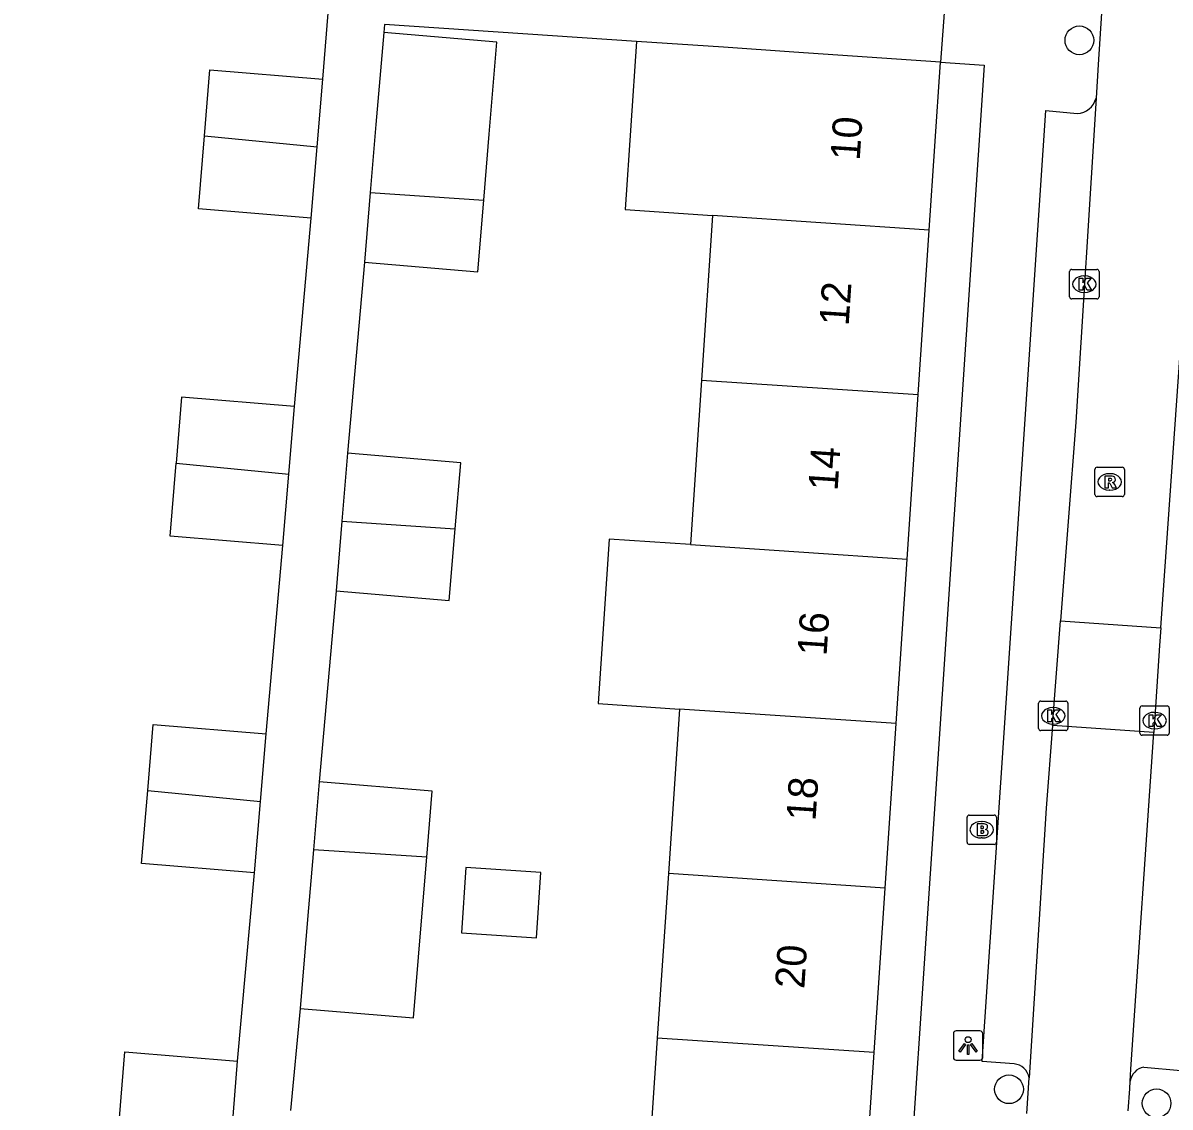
# Model space of a CAD drawing. Extents: x 162250 to 162654, y 380744 to 381605.
# Drawn here: x 162338.01 to 162377.07, y 380830.57 to 380867.49 of the extents above; entities that cross this region are included whole.
import ezdxf

# ---------------------------------------------------------------- set-up
doc = ezdxf.new("R2010")
doc.units = 0
for name, color, linetype in [('IMGEO_Boom', 7, 'Continuous'), ('IMGEO_Brandkraan', 7, 'Continuous'), ('IMGEO_Kolk', 7, 'Continuous'), ('IMGEO_Lichtpunt', 7, 'Continuous'), ('IMGEO_Pand', 7, 'Continuous'), ('IMGEO_Pand_nummerreeks', 7, 'Continuous'), ('IMGEO_Rijbaan_lokaal_open', 7, 'Continuous'), ('IMGEO_Rioolput', 7, 'Continuous'), ('IMGEO_Voetpad_open', 7, 'Continuous')]:
    doc.layers.add(name, color=color, linetype=linetype)

msp = doc.modelspace()

# ---------------------------------------------------------------- linework, layer by layer
at = {"layer": 'IMGEO_Boom'}
for centre in [(162373.988, 380866.894), (162371.59, 380831.172), (162376.616, 380830.694)]:
    msp.add_circle(centre, 0.489, dxfattribs=at)
at = {"layer": 'IMGEO_Brandkraan'}
for p, q in [((162370.162, 380839.584), (162370.162, 380840.436)), ((162370.237, 380840.51), (162371.089, 380840.51)), ((162370.65, 380840.29), (162370.675, 380840.29)), ((162371.163, 380840.436), (162371.163, 380839.584)), ((162371.089, 380839.51), (162370.237, 380839.51)), ((162370.673, 380839.73), (162370.648, 380839.73))]:
    msp.add_line(p, q, dxfattribs=at)
for points in [[(162370.162, 380839.584), (162370.162, 380840.436)], [(162370.237, 380840.51), (162371.089, 380840.51)], [(162370.51, 380840.21), (162370.51, 380839.81), (162370.723, 380839.81)], [(162370.741, 380840.21), (162370.51, 380840.21)], [(162371.163, 380840.436), (162371.163, 380839.584)], [(162370.689, 380840.129), (162370.635, 380840.129), (162370.635, 380840.053)], [(162370.635, 380840.053), (162370.688, 380840.053)], [(162370.697, 380839.977), (162370.635, 380839.977), (162370.635, 380839.896)], [(162370.635, 380839.896), (162370.697, 380839.896)], [(162371.089, 380839.51), (162370.237, 380839.51)]]:
    msp.add_lwpolyline(points, dxfattribs=at)
for centre, radius, start, end in [((162370.239, 380840.434), 0.0765, 91.552, 178.448), ((162370.239, 380840.434), 0.0765, 91.552, 178.448), ((162370.745, 380840.065), 0.145, 59.4692, 91.5367), ((162370.77, 380840.112), 0.0922, 285.5137, 58.1501), ((162371.087, 380840.434), 0.0765, 1.552, 88.448), ((162371.087, 380840.434), 0.0765, 1.552, 88.448), ((162370.69, 380840.091), 0.0379, 267.8285, 90.9355), ((162370.698, 380839.936), 0.0404, 269.8759, 90.5077), ((162370.729, 380840.061), 0.251, 268.6676, 293.5347), ((162370.775, 380839.92), 0.105, 301.3115, 78.989), ((162370.239, 380839.586), 0.0765, 181.552, 268.448), ((162370.239, 380839.586), 0.0765, 181.552, 268.448), ((162371.087, 380839.586), 0.0765, 271.552, 358.448), ((162371.087, 380839.586), 0.0765, 271.552, 358.448)]:
    msp.add_arc(centre, radius, start, end, dxfattribs=at)
for centre, major_axis, ratio, start_param, end_param in [((162370.649, 380840.01), (-0.387, 0.002), 0.722429, 4.712389, 7.853982), ((162370.674, 380840.01), (-0.39, 0.002), 0.717154, 1.570796, 4.712389)]:
    msp.add_ellipse(centre, major_axis=major_axis, ratio=ratio, start_param=start_param, end_param=end_param, dxfattribs=at)
at = {"layer": 'IMGEO_Kolk'}
for p, q in [((162373.656, 380858.164), (162373.656, 380859.016)), ((162373.731, 380859.09), (162374.583, 380859.09)), ((162374.657, 380859.016), (162374.657, 380858.164)), ((162374.144, 380858.87), (162374.169, 380858.87)), ((162374.167, 380858.31), (162374.142, 380858.31)), ((162374.583, 380858.09), (162373.731, 380858.09)), ((162372.597, 380843.464), (162372.597, 380844.316)), ((162372.672, 380844.39), (162373.524, 380844.39)), ((162373.085, 380844.17), (162373.11, 380844.17)), ((162373.598, 380844.316), (162373.598, 380843.464)), ((162376.047, 380843.302), (162376.047, 380844.154)), ((162376.122, 380844.228), (162376.974, 380844.228)), ((162377.048, 380844.154), (162377.048, 380843.302)), ((162376.535, 380844.008), (162376.56, 380844.008)), ((162373.524, 380843.39), (162372.672, 380843.39)), ((162373.108, 380843.61), (162373.083, 380843.61)), ((162376.558, 380843.448), (162376.533, 380843.448)), ((162376.974, 380843.228), (162376.122, 380843.228))]:
    msp.add_line(p, q, dxfattribs=at)
for points in [[(162373.656, 380858.164), (162373.656, 380859.016)], [(162373.731, 380859.09), (162374.583, 380859.09)], [(162374.657, 380859.016), (162374.657, 380858.164)], [(162373.977, 380858.79), (162374.1, 380858.79), (162374.1, 380858.639), (162374.23, 380858.79), (162374.394, 380858.79), (162374.248, 380858.639), (162374.401, 380858.39), (162374.249, 380858.39), (162374.164, 380858.554), (162374.1, 380858.487), (162374.1, 380858.39), (162373.977, 380858.39), (162373.977, 380858.79)], [(162374.583, 380858.09), (162373.731, 380858.09)], [(162372.597, 380843.464), (162372.597, 380844.316)], [(162372.672, 380844.39), (162373.524, 380844.39)], [(162372.918, 380844.09), (162373.041, 380844.09), (162373.041, 380843.939), (162373.171, 380844.09), (162373.335, 380844.09), (162373.189, 380843.939), (162373.342, 380843.69), (162373.19, 380843.69), (162373.105, 380843.854), (162373.041, 380843.787), (162373.041, 380843.69), (162372.918, 380843.69), (162372.918, 380844.09)], [(162373.598, 380844.316), (162373.598, 380843.464)], [(162376.047, 380843.302), (162376.047, 380844.154)], [(162376.122, 380844.228), (162376.974, 380844.228)], [(162377.048, 380844.154), (162377.048, 380843.302)], [(162376.368, 380843.928), (162376.491, 380843.928), (162376.491, 380843.777), (162376.621, 380843.928), (162376.785, 380843.928), (162376.639, 380843.777), (162376.792, 380843.528), (162376.64, 380843.528), (162376.555, 380843.692), (162376.491, 380843.625), (162376.491, 380843.528), (162376.368, 380843.528), (162376.368, 380843.928)], [(162373.524, 380843.39), (162372.672, 380843.39)], [(162376.974, 380843.228), (162376.122, 380843.228)]]:
    msp.add_lwpolyline(points, dxfattribs=at)
for centre, start, end in [((162373.733, 380859.014), 91.552, 178.448), ((162373.733, 380859.014), 91.552, 178.448), ((162374.581, 380859.014), 1.552, 88.448), ((162374.581, 380859.014), 1.552, 88.448), ((162373.733, 380858.166), 181.552, 268.448), ((162373.733, 380858.166), 181.552, 268.448), ((162374.581, 380858.166), 271.552, 358.448), ((162374.581, 380858.166), 271.552, 358.448), ((162372.674, 380844.314), 91.552, 178.448), ((162372.674, 380844.314), 91.552, 178.448), ((162373.522, 380844.314), 1.552, 88.448), ((162373.522, 380844.314), 1.552, 88.448), ((162376.124, 380844.152), 91.552, 178.448), ((162376.124, 380844.152), 91.552, 178.448), ((162376.972, 380844.152), 1.552, 88.448), ((162376.972, 380844.152), 1.552, 88.448), ((162372.674, 380843.466), 181.552, 268.448), ((162372.674, 380843.466), 181.552, 268.448), ((162373.522, 380843.466), 271.552, 358.448), ((162373.522, 380843.466), 271.552, 358.448), ((162376.124, 380843.304), 181.552, 268.448), ((162376.124, 380843.304), 181.552, 268.448), ((162376.972, 380843.304), 271.552, 358.448), ((162376.972, 380843.304), 271.552, 358.448)]:
    msp.add_arc(centre, 0.0765, start, end, dxfattribs=at)
for centre, major_axis, ratio, start_param, end_param in [((162374.143, 380858.59), (-0.387, 0.002), 0.722429, 4.712389, 7.853982), ((162374.168, 380858.59), (-0.39, 0.002), 0.717154, 1.570796, 4.712389), ((162373.084, 380843.89), (-0.387, 0.002), 0.722429, 4.712389, 7.853982), ((162373.109, 380843.89), (-0.39, 0.002), 0.717154, 1.570796, 4.712389), ((162376.534, 380843.728), (-0.387, 0.002), 0.722429, 4.712389, 7.853982), ((162376.559, 380843.728), (-0.39, 0.002), 0.717154, 1.570796, 4.712389)]:
    msp.add_ellipse(centre, major_axis=major_axis, ratio=ratio, start_param=start_param, end_param=end_param, dxfattribs=at)
at = {"layer": 'IMGEO_Lichtpunt'}
for p, q in [((162370.601, 380833.159), (162369.793, 380833.159)), ((162370.601, 380833.159), (162369.793, 380833.159)), ((162369.699, 380833.064), (162369.699, 380832.257)), ((162369.699, 380833.064), (162369.699, 380832.257)), ((162370.695, 380832.257), (162370.695, 380833.064)), ((162370.695, 380832.257), (162370.695, 380833.064)), ((162369.793, 380832.163), (162370.601, 380832.163)), ((162369.793, 380832.163), (162370.601, 380832.163))]:
    msp.add_line(p, q, dxfattribs=at)
for points in [[(162370.073, 380832.728), (162370.112, 380832.7), (162369.924, 380832.438), (162369.886, 380832.465), (162370.073, 380832.728)], [(162370.175, 380832.68), (162370.222, 380832.68), (162370.222, 380832.358), (162370.175, 380832.358), (162370.175, 380832.68)], [(162370.285, 380832.7), (162370.323, 380832.727), (162370.51, 380832.465), (162370.471, 380832.437), (162370.285, 380832.7)]]:
    msp.add_lwpolyline(points, dxfattribs=at)
msp.add_circle((162370.198, 380832.862), 0.0994, dxfattribs=at)
for centre, start, end in [((162369.793, 380833.064), 90, 180), ((162369.793, 380833.064), 90, 180), ((162370.601, 380833.064), 0, 90), ((162370.601, 380833.064), 0, 90), ((162369.793, 380832.257), 180, 270), ((162369.793, 380832.257), 180, 270), ((162370.601, 380832.257), 270, 0), ((162370.601, 380832.257), 270, 360)]:
    msp.add_arc(centre, 0.0946, start, end, dxfattribs=at)
at = {"layer": 'IMGEO_Pand'}
for points in [[(162350.298, 380867.159), (162350.036, 380864.023), (162349.843, 380861.713)], [(162353.704, 380861.454), (162353.891, 380863.701), (162354.152, 380866.837), (162350.298, 380867.159)], [(162358.908, 380866.856), (162358.525, 380861.128), (162361.491, 380860.93)], [(162369.257, 380866.155), (162364.269, 380866.488), (162361.874, 380866.658), (162358.908, 380866.856)], [(162368.874, 380860.433), (162369.257, 380866.155)], [(162344.195, 380863.647), (162344.382, 380865.892), (162348.221, 380865.572)], [(162348.029, 380863.266), (162348.221, 380865.572)], [(162347.826, 380860.838), (162343.987, 380861.158), (162344.195, 380863.647)], [(162344.195, 380863.647), (162348.029, 380863.266)], [(162347.826, 380860.838), (162348.029, 380863.266)], [(162349.843, 380861.713), (162349.645, 380859.334)], [(162349.843, 380861.713), (162353.704, 380861.454)], [(162349.645, 380859.334), (162353.5, 380859.013), (162353.704, 380861.454)], [(162361.491, 380860.93), (162361.116, 380855.325)], [(162368.874, 380860.433), (162361.491, 380860.93)], [(162368.499, 380854.829), (162368.874, 380860.433)], [(162361.116, 380855.325), (162360.741, 380849.724)], [(162361.116, 380855.325), (162368.499, 380854.829)], [(162347.256, 380854.422), (162343.417, 380854.742), (162343.23, 380852.498)], [(162368.125, 380849.228), (162368.499, 380854.829)], [(162347.064, 380852.116), (162347.256, 380854.422)], [(162349.067, 380852.831), (162348.874, 380850.521)], [(162352.735, 380850.262), (162352.922, 380852.509), (162349.067, 380852.831)], [(162346.861, 380849.688), (162343.022, 380850.008), (162343.23, 380852.498)], [(162343.23, 380852.498), (162347.064, 380852.116)], [(162346.861, 380849.688), (162347.064, 380852.116)], [(162348.874, 380850.521), (162348.676, 380848.142)], [(162348.874, 380850.521), (162352.735, 380850.262)], [(162348.676, 380848.142), (162352.531, 380847.821), (162352.735, 380850.262)], [(162360.741, 380849.724), (162357.972, 380849.909), (162357.597, 380844.307), (162360.366, 380844.122)], [(162360.741, 380849.724), (162368.125, 380849.228)], [(162367.75, 380843.625), (162368.125, 380849.228)], [(162360.366, 380844.122), (162359.991, 380838.519)], [(162367.75, 380843.625), (162360.366, 380844.122)], [(162342.265, 380841.348), (162342.452, 380843.593), (162346.291, 380843.273)], [(162367.375, 380838.022), (162367.75, 380843.625)], [(162346.099, 380840.967), (162346.291, 380843.273)], [(162345.896, 380838.539), (162342.057, 380838.859), (162342.265, 380841.348)], [(162342.265, 380841.348), (162346.099, 380840.967)], [(162348.099, 380841.641), (162347.906, 380839.331)], [(162351.767, 380839.072), (162351.954, 380841.319), (162348.099, 380841.641)], [(162345.896, 380838.539), (162346.099, 380840.967)], [(162347.906, 380839.331), (162347.708, 380836.952), (162347.456, 380833.924)], [(162347.456, 380833.924), (162351.31, 380833.603), (162351.563, 380836.631), (162351.767, 380839.072)], [(162351.767, 380839.072), (162347.906, 380839.331)], [(162352.948, 380836.504), (162355.498, 380836.333), (162355.647, 380838.554), (162353.097, 380838.726), (162352.948, 380836.504)], [(162359.991, 380838.519), (162359.616, 380832.916)], [(162367.375, 380838.022), (162359.991, 380838.519)], [(162367, 380832.42), (162367.375, 380838.022)], [(162359.616, 380832.916), (162359.241, 380827.313)], [(162367, 380832.42), (162359.616, 380832.916)], [(162341.3, 380830.2), (162341.487, 380832.444), (162345.326, 380832.124)], [(162366.625, 380826.817), (162367, 380832.42)], [(162345.134, 380829.818), (162345.326, 380832.124)]]:
    msp.add_lwpolyline(points, dxfattribs=at)
at = {"layer": 'IMGEO_Rijbaan_lokaal_open'}
for points in [[(162374.744, 380867.824), (162374.627, 380866.068), (162374.555, 380864.924)], [(162374.555, 380864.924), (162373.864, 380853.89), (162373.347, 380847.122)], [(162376.764, 380846.886), (162377.501, 380857.359), (162378.012, 380864.96)], [(162373.075, 380843.562), (162373.347, 380847.122)], [(162373.347, 380847.122), (162376.764, 380846.886)], [(162376.764, 380846.886), (162376.721, 380846.28), (162376.521, 380843.324)], [(162373.075, 380843.562), (162372.859, 380840.742), (162372.276, 380831.566)], [(162376.521, 380843.324), (162373.075, 380843.562)], [(162375.716, 380831.445), (162375.743, 380831.854), (162376.521, 380843.324)], [(162372.199, 380830.348), (162372.276, 380831.566)], [(162375.65, 380830.442), (162375.7, 380831.192), (162375.716, 380831.445)]]:
    msp.add_lwpolyline(points, dxfattribs=at)
at = {"layer": 'IMGEO_Rioolput'}
for p, q in [((162374.518, 380851.431), (162374.518, 380852.283)), ((162374.593, 380852.357), (162375.445, 380852.357)), ((162375.519, 380852.283), (162375.519, 380851.431)), ((162375.006, 380852.137), (162375.031, 380852.137)), ((162375.029, 380851.577), (162375.004, 380851.577)), ((162375.445, 380851.357), (162374.593, 380851.357))]:
    msp.add_line(p, q, dxfattribs=at)
for points in [[(162374.518, 380851.431), (162374.518, 380852.283)], [(162374.593, 380852.357), (162375.445, 380852.357)], [(162375.519, 380852.283), (162375.519, 380851.431)], [(162375.107, 380852.055), (162374.855, 380852.057), (162374.855, 380851.657)], [(162375.033, 380851.976), (162374.979, 380851.976), (162374.979, 380851.895)], [(162374.979, 380851.895), (162375.031, 380851.895)], [(162374.855, 380851.657), (162374.979, 380851.657), (162374.979, 380851.819), (162374.99, 380851.819)], [(162375.037, 380851.79), (162375.108, 380851.657), (162375.248, 380851.657), (162375.183, 380851.783)], [(162375.445, 380851.357), (162374.593, 380851.357)]]:
    msp.add_lwpolyline(points, dxfattribs=at)
for centre, radius, start, end in [((162374.595, 380852.281), 0.0765, 91.552, 178.448), ((162374.595, 380852.281), 0.0765, 91.552, 178.448), ((162375.443, 380852.281), 0.0765, 1.552, 88.448), ((162375.443, 380852.281), 0.0765, 1.552, 88.448), ((162375.015, 380852.084), 0.19, 274.7715, 282.9687), ((162375.039, 380851.88), 0.0964, 77.0061, 93.1865), ((162375.053, 380851.937), 0.0378, 276.6634, 79.6772), ((162375.106, 380851.945), 0.109, 350.3612, 89.416), ((162375.104, 380851.945), 0.112, 277.5842, 350.9817), ((162374.989, 380851.766), 0.0533, 26.0293, 88.6989), ((162375.088, 380851.73), 0.108, 29.5134, 73.7905), ((162374.595, 380851.433), 0.0765, 181.552, 268.448), ((162374.595, 380851.433), 0.0765, 181.552, 268.448), ((162375.443, 380851.433), 0.0765, 271.552, 358.448), ((162375.443, 380851.433), 0.0765, 271.552, 358.448)]:
    msp.add_arc(centre, radius, start, end, dxfattribs=at)
for centre, major_axis, ratio, start_param, end_param in [((162375.005, 380851.857), (-0.387, 0.002), 0.722429, 4.712389, 7.853982), ((162375.03, 380851.857), (-0.39, 0.002), 0.717154, 1.570796, 4.712389)]:
    msp.add_ellipse(centre, major_axis=major_axis, ratio=ratio, start_param=start_param, end_param=end_param, dxfattribs=at)
at = {"layer": 'IMGEO_Voetpad_open'}
for points in [[(162348.221, 380865.572), (162348.503, 380868.957), (162336.901, 380870.115)], [(162369.409, 380868.137), (162369.257, 380866.155)], [(162358.908, 380866.856), (162350.321, 380867.431), (162350.298, 380867.159)], [(162369.257, 380866.155), (162370.749, 380866.049), (162366.24, 380798.568), (162364.743, 380798.685)], [(162371.765, 380832.039), (162370.673, 380832.122), (162372.849, 380864.507), (162373.915, 380864.399)], [(162376.183, 380831.92), (162377.442, 380831.816), (162377.563, 380833.263), (162379.704, 380864.148), (162378.689, 380864.243)], [(162347.256, 380854.422), (162347.826, 380860.838)], [(162349.645, 380859.334), (162349.067, 380852.831)], [(162346.291, 380843.273), (162346.861, 380849.688)], [(162348.676, 380848.142), (162348.099, 380841.641)], [(162345.326, 380832.124), (162345.896, 380838.539)], [(162347.456, 380833.924), (162347.13, 380830.45)]]:
    msp.add_lwpolyline(points, dxfattribs=at)
for centre, radius, start, end in [((162373.881, 380865.093), 0.695, 272.7966, 345.9283), ((162371.703, 380831.459), 0.583, 10.5538, 83.8693), ((162376.27, 380831.367), 0.56, 98.9665, 172.0066)]:
    msp.add_arc(centre, radius, start, end, dxfattribs=at)

# ---------------------------------------------------------------- texts
at = {"layer": 'IMGEO_Pand_nummerreeks'}
for s, rotation, p in [('10', 86.1729, (162366.505, 380862.781)), ('12', 86.1724, (162366.129, 380857.153)), ('14', 86.1724, (162365.753, 380851.533)), ('16', 86.1724, (162365.377, 380845.911)), ('18', 86.1724, (162365.001, 380840.291)), ('20', 86.1724, (162364.619, 380834.578))]:
    msp.add_text(s, height=1, rotation=rotation, dxfattribs=at).set_placement(p)

doc.saveas('drawing.dxf')
